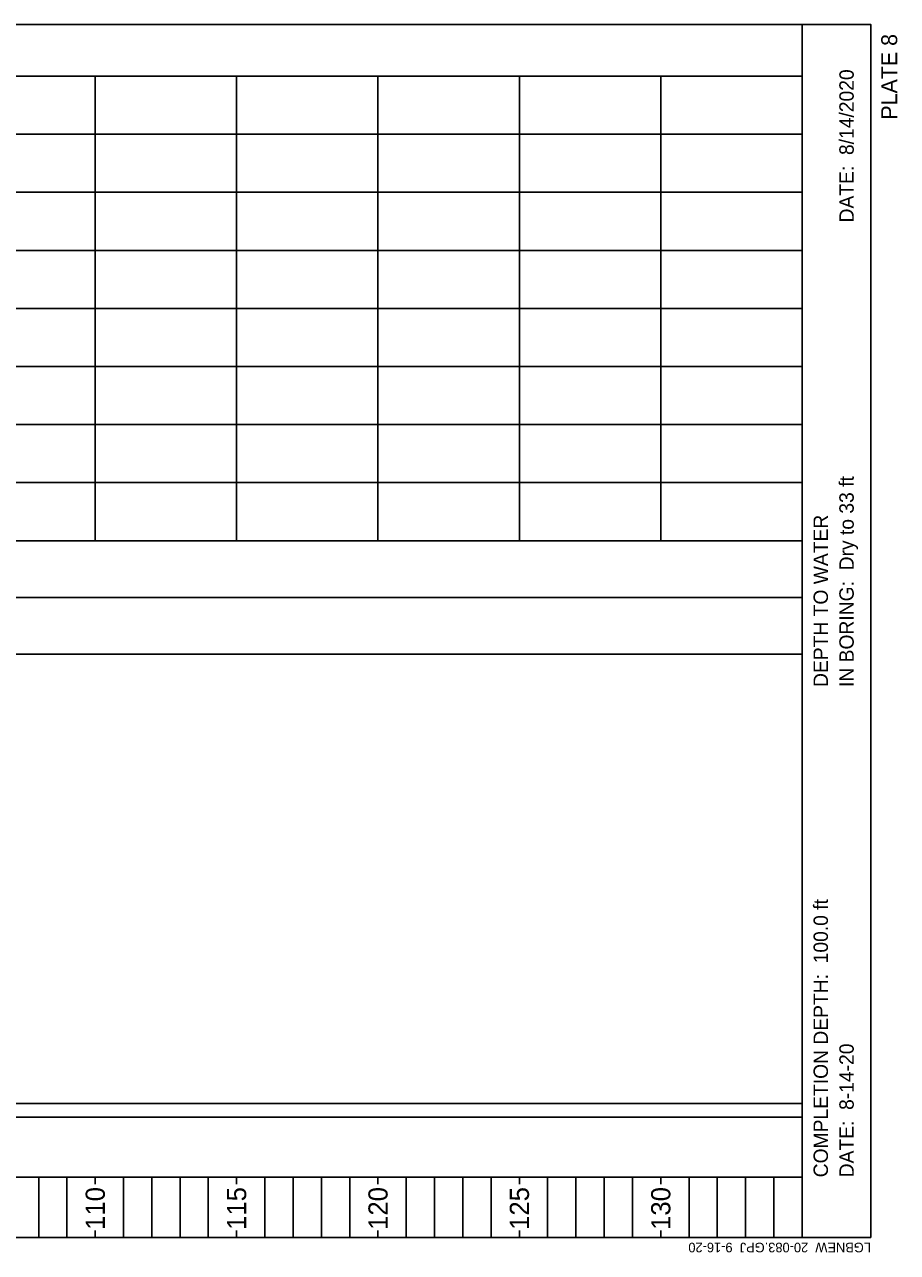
# Model space of a CAD drawing. Extents: x 1313964 to 1316843, y 2087046 to 2096619.
# Drawn here: x 1314106.79 to 1314137.66, y 2089927.64 to 2089971.04 of the extents above; entities that cross this region are included whole.
import ezdxf

# ---------------------------------------------------------------- set-up
doc = ezdxf.new("R2010")
doc.units = 0
doc.layers.add('B-Sub-Contour', color=7, linetype='Continuous')

msp = doc.modelspace()

# ---------------------------------------------------------------- linework, layer by layer
at = {"layer": 'B-Sub-Contour'}
for points in [[(1314136.725, 2089928.164), (1314136.725, 2089971.035), (1314075.306, 2089971.035), (1314075.306, 2089928.164), (1314136.725, 2089928.164)], [(1314134.292, 2089928.164), (1314134.292, 2089971.035)], [(1314134.292, 2089969.211), (1314082.603, 2089969.211)], [(1314134.292, 2089969.211), (1314089.292, 2089969.211)], [(1314109.292, 2089952.792), (1314109.292, 2089969.211)], [(1314114.292, 2089952.792), (1314114.292, 2089969.211)], [(1314119.292, 2089952.792), (1314119.292, 2089969.211)], [(1314124.292, 2089952.792), (1314124.292, 2089969.211)], [(1314129.292, 2089952.792), (1314129.292, 2089969.211)], [(1314134.292, 2089952.792), (1314134.292, 2089969.211)], [(1314134.292, 2089967.159), (1314089.292, 2089967.159)], [(1314134.292, 2089965.106), (1314089.292, 2089965.106)], [(1314134.292, 2089963.054), (1314089.292, 2089963.054)], [(1314134.292, 2089961.002), (1314089.292, 2089961.002)], [(1314134.292, 2089958.949), (1314089.292, 2089958.949)], [(1314134.292, 2089956.897), (1314089.292, 2089956.897)], [(1314134.292, 2089954.845), (1314089.292, 2089954.845)], [(1314134.292, 2089952.792), (1314082.603, 2089952.792)], [(1314134.292, 2089952.792), (1314089.292, 2089952.792)], [(1314134.292, 2089950.785), (1314082.603, 2089950.785)], [(1314134.292, 2089948.779), (1314082.603, 2089948.779)], [(1314134.292, 2089932.907), (1314089.292, 2089932.907)], [(1314134.292, 2089932.421), (1314082.603, 2089932.421)], [(1314134.292, 2089930.292), (1314082.603, 2089930.292)], [(1314107.292, 2089928.164), (1314107.292, 2089930.292)], [(1314107.292, 2089928.164), (1314107.292, 2089930.292)], [(1314108.292, 2089928.164), (1314108.292, 2089930.292)], [(1314109.292, 2089930.049), (1314109.292, 2089930.292)], [(1314109.292, 2089930.049), (1314109.292, 2089930.292)], [(1314110.292, 2089928.164), (1314110.292, 2089930.292)], [(1314111.292, 2089928.164), (1314111.292, 2089930.292)], [(1314111.292, 2089928.164), (1314111.292, 2089930.292)], [(1314112.292, 2089928.164), (1314112.292, 2089930.292)], [(1314113.292, 2089928.164), (1314113.292, 2089930.292)], [(1314113.292, 2089928.164), (1314113.292, 2089930.292)], [(1314114.292, 2089930.049), (1314114.292, 2089930.292)], [(1314115.292, 2089928.164), (1314115.292, 2089930.292)], [(1314115.292, 2089928.164), (1314115.292, 2089930.292)], [(1314116.292, 2089928.164), (1314116.292, 2089930.292)], [(1314117.292, 2089928.164), (1314117.292, 2089930.292)], [(1314117.292, 2089928.164), (1314117.292, 2089930.292)], [(1314118.292, 2089928.164), (1314118.292, 2089930.292)], [(1314119.292, 2089930.049), (1314119.292, 2089930.292)], [(1314119.292, 2089930.049), (1314119.292, 2089930.292)], [(1314120.292, 2089928.164), (1314120.292, 2089930.292)], [(1314121.292, 2089928.164), (1314121.292, 2089930.292)], [(1314121.292, 2089928.164), (1314121.292, 2089930.292)], [(1314122.292, 2089928.164), (1314122.292, 2089930.292)], [(1314123.292, 2089928.164), (1314123.292, 2089930.292)], [(1314123.292, 2089928.164), (1314123.292, 2089930.292)], [(1314124.292, 2089930.049), (1314124.292, 2089930.292)], [(1314125.292, 2089928.164), (1314125.292, 2089930.292)], [(1314125.292, 2089928.164), (1314125.292, 2089930.292)], [(1314126.292, 2089928.164), (1314126.292, 2089930.292)], [(1314127.292, 2089928.164), (1314127.292, 2089930.292)], [(1314127.292, 2089928.164), (1314127.292, 2089930.292)], [(1314128.292, 2089928.164), (1314128.292, 2089930.292)], [(1314129.292, 2089930.049), (1314129.292, 2089930.292)], [(1314129.292, 2089930.049), (1314129.292, 2089930.292)], [(1314130.292, 2089928.164), (1314130.292, 2089930.292)], [(1314131.292, 2089928.164), (1314131.292, 2089930.292)], [(1314131.292, 2089928.164), (1314131.292, 2089930.292)], [(1314132.292, 2089928.164), (1314132.292, 2089930.292)], [(1314133.292, 2089928.164), (1314133.292, 2089930.292)], [(1314133.292, 2089928.164), (1314133.292, 2089930.292)], [(1314134.292, 2089930.049), (1314134.292, 2089930.292)], [(1314109.292, 2089928.164), (1314109.292, 2089928.407)], [(1314109.292, 2089928.164), (1314109.292, 2089928.407)], [(1314114.292, 2089928.164), (1314114.292, 2089928.407)], [(1314119.292, 2089928.164), (1314119.292, 2089928.407)], [(1314119.292, 2089928.164), (1314119.292, 2089928.407)], [(1314124.292, 2089928.164), (1314124.292, 2089928.407)], [(1314129.292, 2089928.164), (1314129.292, 2089928.407)], [(1314129.292, 2089928.164), (1314129.292, 2089928.407)], [(1314134.292, 2089928.164), (1314134.292, 2089928.407)]]:
    msp.add_lwpolyline(points, dxfattribs=at)

# ---------------------------------------------------------------- texts
for s, height, rotation, p in [('PLATE 8', 0.5655, 90, (1314137.655, 2089967.676)), ('DATE:  8/14/2020', 0.50899, 90, (1314136.117, 2089964.042)), ('IN BORING:  Dry to 33 ft', 0.50899, 90, (1314136.117, 2089947.623)), ('DEPTH TO WATER', 0.50899, 90, (1314135.205, 2089947.623)), ('COMPLETION DEPTH:  100.0 ft', 0.50899, 90, (1314135.205, 2089930.292)), ('DATE:  8-14-20', 0.50899, 90, (1314136.117, 2089930.292)), ('110', 0.6786, 90, (1314109.632, 2089928.434)), ('110', 0.6786, 90, (1314109.632, 2089928.434)), ('115', 0.6786, 90, (1314114.632, 2089928.434)), ('120', 0.6786, 90, (1314119.632, 2089928.434)), ('120', 0.6786, 90, (1314119.632, 2089928.434)), ('125', 0.6786, 90, (1314124.632, 2089928.434)), ('130', 0.6786, 90, (1314129.632, 2089928.434)), ('130', 0.6786, 90, (1314129.632, 2089928.434)), ('LGBNEW  20-083.GPJ  9-16-20', 0.33932, 180, (1314136.725, 2089927.981))]:
    msp.add_text(s, height=height, rotation=rotation, dxfattribs=at).set_placement(p)

doc.saveas('drawing.dxf')
